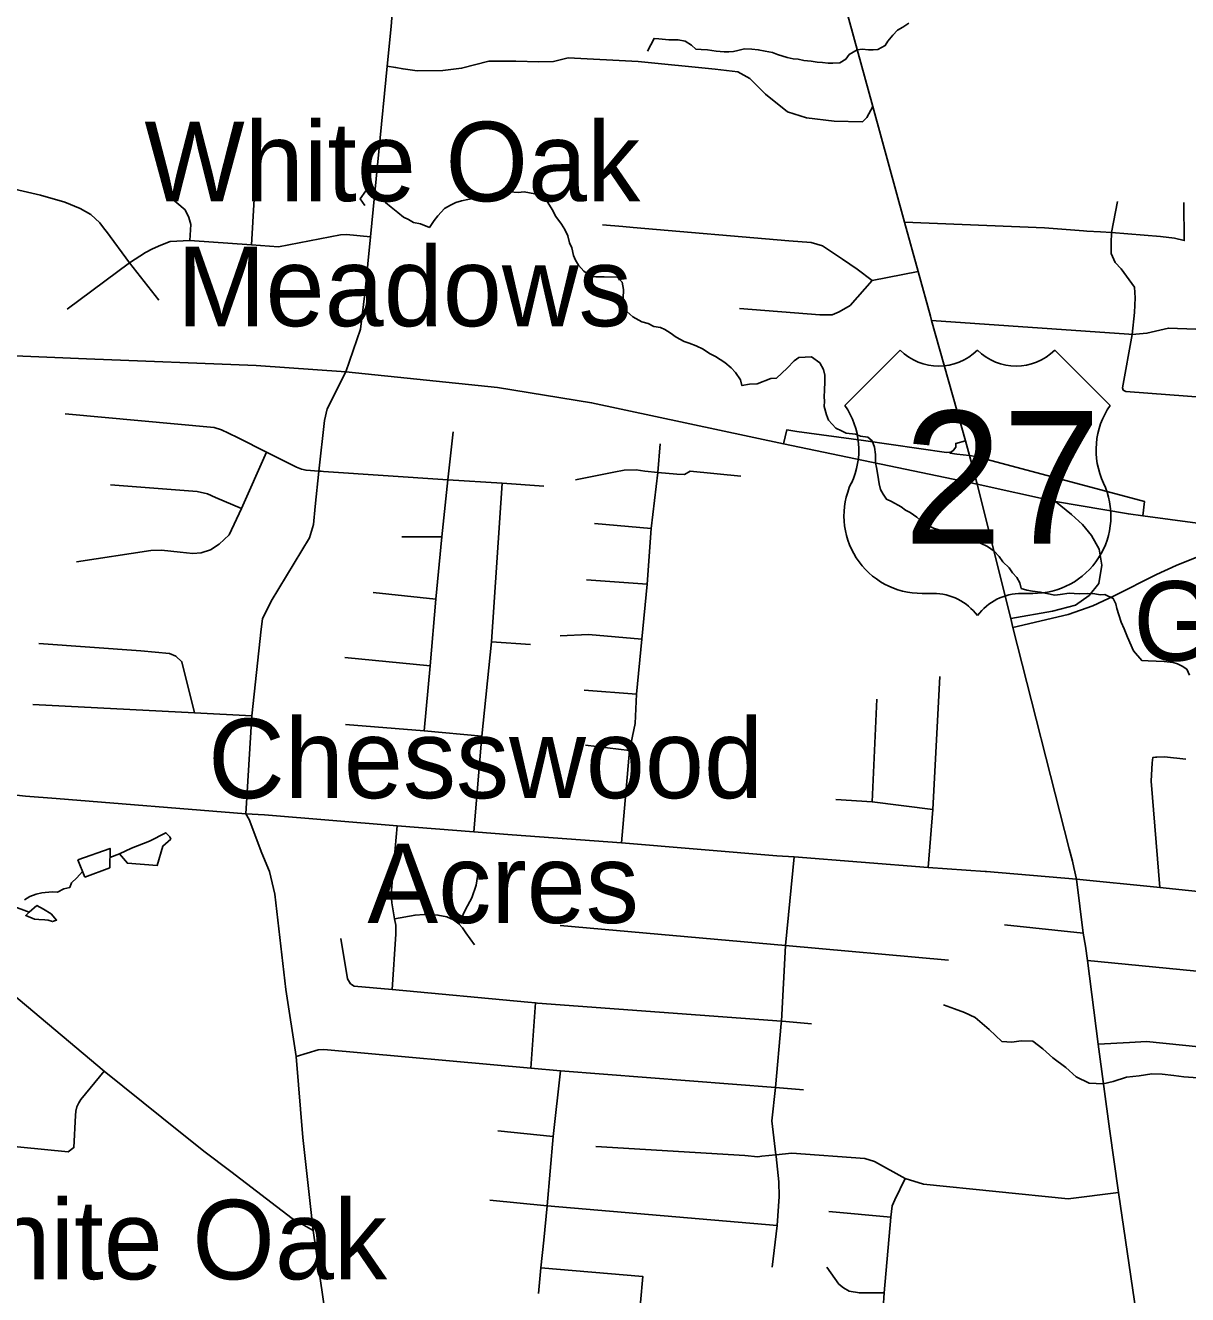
# Model space of a CAD drawing. Extents: x 0 to 69.5, y -4.5 to 22.
# Drawn here: x 3.408 to 4.564, y 15.023 to 16.285 of the extents above; entities that cross this region are included whole.
import ezdxf

# ---------------------------------------------------------------- set-up
doc = ezdxf.new("R2010")
doc.units = 0
for name, color, linetype in [('GM_X_County_Road', 7, 'Continuous'), ('GM_X_Interchange_Ramps', 7, 'Continuous'), ('GM_X_Minor_Lake', 7, 'Continuous'), ('GM_X_Minor_River', 7, 'Continuous'), ('GM_X_State_Route', 7, 'Continuous'), ('GM_X_Township_Subdivision', 7, 'Continuous'), ('GM_X_Unincorporated_Text', 7, 'Continuous'), ('GM_X_US_Location', 7, 'Continuous'), ('GM_X_US_Route', 7, 'Continuous'), ('GM_X_US_Shield', 7, 'Continuous')]:
    doc.layers.add(name, color=color, linetype=linetype)

msp = doc.modelspace()

# ---------------------------------------------------------------- linework, layer by layer
at = {"layer": 'GM_X_County_Road'}
for points in [[(3.6274, 15.5008), (3.6334, 15.5983), (3.6428, 15.6844), (3.6442, 15.6947), (3.6526, 15.7123), (3.6907, 15.7752), (3.6948, 15.7884), (3.6964, 15.8066), (3.7002, 15.8416), (3.7057, 15.8918), (3.7083, 15.9035), (3.7269, 15.9403), (3.7414, 15.9828), (3.7462, 16.0207), (3.7514, 16.0744), (3.7681, 16.2443), (3.7721, 16.2837), (3.7888, 16.4987)], [(3.7681, 16.2443), (3.7764, 16.243), (3.7839, 16.2415), (3.798, 16.2394), (3.8233, 16.2398), (3.8421, 16.2421), (3.8692, 16.2492), (3.8959, 16.2492), (3.9188, 16.2485), (3.9335, 16.2489), (3.9482, 16.2526), (4.0178, 16.2489), (4.0942, 16.2413), (4.1168, 16.2387), (4.1288, 16.2319), (4.1443, 16.2165), (4.1661, 16.1988), (4.1849, 16.1928), (4.2124, 16.1894), (4.2406, 16.1887), (4.2449, 16.193), (4.2509, 16.204)], [(2.0624, 16.1544), (2.0789, 16.1495), (2.3218, 16.0727), (2.3948, 16.0576), (2.5679, 16.0322), (2.6419, 16.0249), (2.8264, 16.0064), (2.913, 15.9963), (3.15, 15.9729), (3.2871, 15.9607), (3.469, 15.9531), (3.6377, 15.9467), (3.7269, 15.9403), (3.8777, 15.9247), (3.9714, 15.9095), (4.1621, 15.8689), (4.3548, 15.8285)], [(4.3548, 15.8285), (4.4326, 15.8115)], [(4.4326, 15.8115), (4.4486, 15.7985), (4.4596, 15.7885), (4.4686, 15.7775), (4.4761, 15.764), (4.4786, 15.748), (4.4756, 15.73), (4.4661, 15.718), (4.4526, 15.7085), (4.4296, 15.7025), (4.3881, 15.6951)], [(3.1437, 15.5578), (3.2132, 15.5475), (3.3147, 15.5315), (3.3657, 15.5231), (3.4084, 15.5185), (3.4388, 15.5162), (3.6274, 15.5008)], [(3.6945, 15.0867), (3.6842, 15.1793), (3.6775, 15.2598), (3.6674, 15.3264), (3.6565, 15.421), (3.6512, 15.4435), (3.6436, 15.4618), (3.631, 15.4952), (3.6274, 15.5008)], [(3.6274, 15.5008), (3.6461, 15.4998), (3.7781, 15.4889), (3.8541, 15.483), (3.8925, 15.4802), (4.001, 15.472), (4.1557, 15.4593), (4.1727, 15.4582), (4.306, 15.4477), (4.3627, 15.4437), (4.3641, 15.4436)], [(4.3641, 15.4436), (4.4536, 15.436)], [(4.4536, 15.436), (4.5333, 15.4281)], [(4.5333, 15.4281), (4.5365, 15.4278), (4.6218, 15.4186), (4.7103, 15.4103), (4.7637, 15.4056), (4.8525, 15.397), (4.9822, 15.3853), (5.1507, 15.3687)], [(3.3884, 15.3276), (3.4866, 15.245), (3.5439, 15.199), (3.5857, 15.1656), (3.6126, 15.1455), (3.6735, 15.0988), (3.6945, 15.0867)], [(3.6945, 15.0867), (3.7086, 14.9889), (3.7089, 14.9865), (3.7134, 14.9601), (3.7288, 14.8681), (3.7325, 14.8589)]]:
    msp.add_lwpolyline(points, dxfattribs=at)
at = {"layer": 'GM_X_Interchange_Ramps'}
for points in [[(4.343, 15.8718), (4.3335, 15.8691), (4.3334, 15.8655), (4.3313, 15.8624), (4.3291, 15.8608), (4.3276, 15.8605), (4.3243, 15.8601), (4.2417, 15.8721), (4.1754, 15.881), (4.1654, 15.8826), (4.1621, 15.8689)], [(4.347, 15.8571), (4.3347, 15.8584), (4.3278, 15.8595), (4.3276, 15.8605)], [(4.5196, 15.797), (4.5211, 15.8115), (4.3546, 15.8557), (4.347, 15.8571)]]:
    msp.add_lwpolyline(points, dxfattribs=at)
at = {"layer": 'GM_X_Minor_Lake'}
for points in [[(3.502, 15.461), (3.5098, 15.4518), (3.5394, 15.4496), (3.5451, 15.4689), (3.5529, 15.4759), (3.5518, 15.4779), (3.5481, 15.4821), (3.5319, 15.4737), (3.5139, 15.4669)], [(3.4673, 15.438), (3.4922, 15.4473), (3.4926, 15.4666), (3.4605, 15.4552)], [(3.5139, 15.4669), (3.502, 15.461)], [(3.4605, 15.4552), (3.4673, 15.438)], [(3.4122, 15.4033), (3.4087, 15.3998), (3.4174, 15.3961), (3.4216, 15.396), (3.4276, 15.3955), (3.431, 15.3951), (3.4352, 15.3938), (3.4394, 15.3953), (3.4338, 15.4015), (3.4263, 15.4062), (3.4197, 15.4099)], [(3.4197, 15.4099), (3.4122, 15.4033)]]:
    msp.add_lwpolyline(points, dxfattribs=at)
at = {"layer": 'GM_X_Minor_River'}
for points in [[(4.2868, 16.2868), (4.281, 16.2831), (4.2756, 16.2799), (4.2709, 16.275), (4.2658, 16.2691), (4.2634, 16.2646), (4.2561, 16.2606), (4.2515, 16.2604), (4.2466, 16.2605), (4.2405, 16.261), (4.2355, 16.2604), (4.2274, 16.2557), (4.2243, 16.2512), (4.2181, 16.2476), (4.2112, 16.247), (4.2067, 16.2471), (4.201, 16.2477), (4.1957, 16.2482), (4.1896, 16.2491), (4.1824, 16.2497), (4.1767, 16.251), (4.1718, 16.2515), (4.1657, 16.2529), (4.1563, 16.2558), (4.1514, 16.2578)], [(4.1514, 16.2578), (4.1439, 16.2592), (4.137, 16.2605), (4.1306, 16.2611), (4.1234, 16.2613), (4.1169, 16.2599), (4.1123, 16.2589), (4.1077, 16.2583), (4.1031, 16.2584), (4.0952, 16.259), (4.0865, 16.2604), (4.0804, 16.2609), (4.0751, 16.2611), (4.0706, 16.265), (4.0643, 16.269), (4.0574, 16.2703), (4.0483, 16.2702), (4.0381, 16.2713), (4.0335, 16.2718), (4.0271, 16.259)], [(4.1657, 15.944), (4.1552, 15.934), (4.1495, 15.9338), (4.136, 15.9285), (4.1284, 15.9279), (4.1208, 15.9266), (4.1194, 15.9324), (4.1143, 15.9397), (4.1102, 15.9444), (4.1039, 15.9495), (4.0945, 15.9555), (4.0885, 15.9587), (4.0822, 15.9627), (4.0754, 15.9663), (4.0683, 15.9688), (4.0634, 15.9705), (4.0555, 15.9749), (4.0495, 15.9792), (4.0443, 15.9824), (4.0398, 15.9845), (4.0334, 15.9854), (4.0277, 15.9882), (4.0213, 15.9899), (4.0123, 15.9951), (4.0064, 16.0003), (4.0031, 16.0064), (4.0029, 16.0133), (4.0032, 16.0221), (4.0019, 16.0293), (3.9967, 16.0344), (3.9837, 16.0348), (3.9758, 16.0346), (3.9705, 16.0355), (3.9637, 16.0403), (3.9582, 16.0465), (3.9553, 16.0512), (3.9535, 16.0558), (3.9518, 16.0635), (3.9493, 16.0685), (3.9476, 16.0754), (3.9447, 16.0819), (3.9414, 16.087), (3.9359, 16.0948), (3.9323, 16.1017), (3.9279, 16.1087), (3.9224, 16.1146), (3.9149, 16.1174), (3.9043, 16.1193), (3.8982, 16.1187), (3.8902, 16.1193), (3.8784, 16.1188), (3.8635, 16.1147), (3.8547, 16.113), (3.842, 16.1103), (3.8363, 16.1086), (3.8309, 16.1061), (3.8251, 16.1028), (3.8184, 16.0954), (3.8149, 16.0909), (3.8101, 16.0838), (3.8011, 16.0875), (3.7943, 16.0888), (3.7894, 16.0916), (3.7842, 16.094), (3.7786, 16.0988), (3.7719, 16.1039), (3.7663, 16.1086), (3.7586, 16.1169), (3.7522, 16.1201), (3.7469, 16.1202), (3.7413, 16.1124), (3.7457, 16.1058)], [(4.5659, 15.6389), (4.5634, 15.6446), (4.5585, 15.6478), (4.554, 15.6499), (4.5495, 15.6515), (4.5408, 15.6525), (4.5248, 15.653), (4.5184, 15.6535), (4.5102, 15.6629), (4.5041, 15.6764), (4.5009, 15.6848), (4.4981, 15.6914), (4.4956, 15.6987), (4.4935, 15.7052), (4.4925, 15.7098), (4.49, 15.7149), (4.4817, 15.7189), (4.4771, 15.7186), (4.4718, 15.7196), (4.4642, 15.7198), (4.4566, 15.7196), (4.4513, 15.7201), (4.4464, 15.7203), (4.4372, 15.719), (4.4319, 15.7184), (4.4239, 15.7201), (4.4175, 15.7214), (4.4099, 15.7224), (4.4043, 15.7233), (4.3986, 15.725), (4.3972, 15.7304), (4.3943, 15.7358), (4.3899, 15.7405), (4.3866, 15.7455), (4.3803, 15.7514), (4.3766, 15.7569), (4.3715, 15.762), (4.3651, 15.7667), (4.358, 15.7699), (4.3392, 15.7773), (4.3301, 15.7795), (4.3165, 15.7833), (4.3112, 15.785), (4.306, 15.7874), (4.3007, 15.7906), (4.2948, 15.7957), (4.2881, 15.8005), (4.2836, 15.8029), (4.2791, 15.806), (4.2697, 15.8113), (4.2645, 15.8137), (4.2612, 15.8187), (4.2587, 15.8234), (4.2573, 15.8291), (4.256, 15.8375), (4.2547, 15.8452), (4.2537, 15.8498), (4.2535, 15.8582), (4.2526, 15.8654), (4.2505, 15.8716), (4.246, 15.8755), (4.2388, 15.8765), (4.2339, 15.8785), (4.2244, 15.8795), (4.2199, 15.8816), (4.2143, 15.8844), (4.2069, 15.8922), (4.2048, 15.8976), (4.2027, 15.9057), (4.2029, 15.911), (4.2026, 15.9156), (4.2028, 15.922), (4.2034, 15.9304), (4.2032, 15.9369), (4.2018, 15.9426), (4.1982, 15.9492), (4.19, 15.9551), (4.1774, 15.9547), (4.1728, 15.9514), (4.1657, 15.944)], [(3.4924, 15.4574), (3.502, 15.461)], [(3.4075, 15.4153), (3.4126, 15.4186), (3.4191, 15.4211), (3.4248, 15.4224), (3.4348, 15.4233), (3.4401, 15.4232), (3.4466, 15.4264), (3.4524, 15.4278), (3.4543, 15.4322), (3.4594, 15.4372), (3.4651, 15.4435)], [(3.3865, 15.4148), (3.3953, 15.4094), (3.4122, 15.4033)], [(4.5741, 15.2384), (4.5604, 15.2395), (4.5502, 15.2409), (4.5388, 15.242), (4.5286, 15.2426), (4.516, 15.2406), (4.5034, 15.239), (4.49, 15.2348), (4.4801, 15.2324), (4.466, 15.2331), (4.4532, 15.2395), (4.4428, 15.2489), (4.4301, 15.2583), (4.4201, 15.2673), (4.41, 15.2748), (4.3986, 15.2754), (4.3891, 15.2741), (4.3792, 15.2747), (4.3666, 15.2865), (4.3528, 15.2986), (4.3423, 15.3034), (4.3321, 15.3071), (4.3212, 15.3111)]]:
    msp.add_lwpolyline(points, dxfattribs=at)
at = {"layer": 'GM_X_State_Route'}
for points in [[(4.4326, 15.8115), (4.5051, 15.799), (4.5196, 15.797), (4.6332, 15.782)], [(4.3903, 15.6863), (4.4453, 15.699), (4.4698, 15.7077), (4.4911, 15.7177), (4.5331, 15.7387), (4.5528, 15.7478), (4.5732, 15.7562), (4.5922, 15.7616), (4.6126, 15.7705), (4.6332, 15.782)]]:
    msp.add_lwpolyline(points, dxfattribs=at)
at = {"layer": 'GM_X_Township_Subdivision'}
for points in [[(3.4871, 16.0822), (3.4822, 16.0885), (3.4734, 16.0966), (3.4629, 16.1028), (3.4476, 16.1091), (3.4233, 16.1159), (3.4019, 16.1209), (3.362, 16.1302), (3.3606, 16.1298)], [(3.5718, 16.0708), (3.5727, 16.0867), (3.5708, 16.0938), (3.5671, 16.1013), (3.5487, 16.1168)], [(3.6331, 16.0664), (3.6359, 16.1119)], [(4.4605, 16.0806), (4.4639, 16.0803), (4.4773, 16.0796), (4.4885, 16.0787), (4.537, 16.0747), (4.5509, 16.0731), (4.5607, 16.0708), (4.5604, 16.1085)], [(4.4944, 16.1096), (4.4885, 16.0787), (4.4881, 16.0683), (4.488, 16.0579), (4.492, 16.0491), (4.498, 16.0426), (4.5111, 16.0246), (4.5119, 16.014), (4.5111, 15.9993), (4.5088, 15.9773), (4.4992, 15.9245), (4.4999, 15.9222), (4.5025, 15.9206), (4.669, 15.9083), (4.7263, 15.9033)], [(4.2826, 16.089), (4.4218, 16.0834), (4.4605, 16.0806)], [(3.4498, 16.0027), (3.5117, 16.0487), (3.5276, 16.059), (3.5347, 16.0627), (3.543, 16.0662), (3.5522, 16.0699), (3.5718, 16.0708), (3.6331, 16.0664), (3.6601, 16.0646), (3.7217, 16.0764), (3.7277, 16.0769), (3.7514, 16.0744)], [(3.541, 16.0114), (3.5117, 16.0487), (3.489, 16.0798), (3.4871, 16.0822)], [(4.0025, 16.0848), (3.9822, 16.0866)], [(4.2961, 16.0399), (4.2505, 16.0312), (4.2355, 16.0424), (4.2208, 16.0524), (4.2011, 16.0656), (4.1896, 16.0689), (4.1676, 16.0707), (4.0126, 16.0839), (4.0025, 16.0848)], [(4.1185, 16.0034), (4.1982, 15.997), (4.2105, 15.9971), (4.2175, 16.0001), (4.2284, 16.0064), (4.2505, 16.0312)], [(4.3094, 15.9915), (4.5055, 15.9776)], [(4.5055, 15.9776), (4.5088, 15.9773), (4.5235, 15.9786), (4.545, 15.9838), (4.5904, 15.982), (4.6449, 15.9751), (4.6518, 15.9745)], [(3.448, 15.8985), (3.5959, 15.885), (3.6034, 15.8826), (3.6102, 15.8793), (3.6199, 15.8746), (3.6481, 15.8604), (3.678, 15.8454), (3.6829, 15.8434), (3.6874, 15.8425), (3.7002, 15.8416), (3.7025, 15.8415), (3.7048, 15.8413)], [(3.8047, 15.5833), (3.8107, 15.6481), (3.8165, 15.7144), (3.8224, 15.7763), (3.8285, 15.8331), (3.8336, 15.8806)], [(3.6481, 15.8604), (3.6231, 15.8043), (3.6108, 15.7783), (3.6011, 15.7689), (3.5923, 15.7634), (3.5831, 15.7604), (3.5747, 15.7598), (3.5621, 15.761), (3.5436, 15.7629), (3.5332, 15.7628), (3.459, 15.7513)], [(4.001, 15.472), (4.0089, 15.5639), (4.0147, 15.5907), (4.0159, 15.62), (4.0213, 15.6745), (4.0266, 15.7292), (4.0305, 15.7846), (4.0373, 15.8404), (4.0397, 15.8686)], [(3.7048, 15.8413), (3.8285, 15.8331), (3.8824, 15.8295), (3.9238, 15.8267)], [(3.9555, 15.8328), (3.9935, 15.8407), (4.0037, 15.8424), (4.0156, 15.8428), (4.0244, 15.8417), (4.0373, 15.8404), (4.0562, 15.8385), (4.0639, 15.8383), (4.0695, 15.8416), (4.1198, 15.8367)], [(3.6231, 15.8043), (3.5973, 15.8153), (3.5895, 15.8191), (3.5792, 15.8213), (3.493, 15.8281)], [(3.8541, 15.483), (3.8621, 15.5782), (3.8718, 15.672), (3.8824, 15.8295)], [(4.0305, 15.7846), (3.9744, 15.7894)], [(3.8224, 15.7763), (3.7825, 15.7763)], [(3.9662, 15.7337), (4.0266, 15.7292)], [(3.8165, 15.7144), (3.7542, 15.7208)], [(3.8718, 15.672), (3.9107, 15.6694)], [(3.9401, 15.6778), (3.9683, 15.6793), (4.0213, 15.6745)], [(3.5764, 15.6013), (3.564, 15.6521), (3.5579, 15.6576), (3.5517, 15.6602), (3.5231, 15.6629), (3.4216, 15.6702)], [(3.8107, 15.6481), (3.726, 15.6562)], [(4.306, 15.4477), (4.3107, 15.5051), (4.3175, 15.6376)], [(4.0159, 15.62), (3.9639, 15.6238)], [(3.6334, 15.5983), (3.5764, 15.6013), (3.4156, 15.6096)], [(4.2504, 15.5127), (4.255, 15.6149)], [(3.8621, 15.5782), (3.8047, 15.5833), (3.7268, 15.5897)], [(4.0089, 15.5639), (3.9654, 15.5691)], [(4.5321, 15.5571), (4.5335, 15.5572), (4.5412, 15.5577), (4.5624, 15.5552)], [(4.5365, 15.4278), (4.5278, 15.5333), (4.5288, 15.5516), (4.5293, 15.5568), (4.5321, 15.5571)], [(4.3107, 15.5051), (4.2504, 15.5127), (4.2141, 15.5153)], [(3.7732, 15.3262), (3.7768, 15.3814), (3.7766, 15.3901), (3.7754, 15.3964), (3.7746, 15.4004), (3.7726, 15.4123), (3.772, 15.421), (3.7729, 15.4327), (3.7781, 15.4889)], [(4.1727, 15.4582), (4.1643, 15.37), (4.1602, 15.2947), (4.16, 15.2925)], [(3.8393, 15.3915), (3.8461, 15.4059), (3.8524, 15.4175), (3.8565, 15.4299), (3.8592, 15.4473)], [(3.7754, 15.3964), (3.7959, 15.4003), (3.8049, 15.401), (3.8059, 15.401)], [(3.8059, 15.401), (3.8094, 15.401), (3.8186, 15.4003), (3.8273, 15.3984), (3.8341, 15.3956), (3.8393, 15.3915), (3.8429, 15.3875), (3.8464, 15.3826), (3.855, 15.3707)], [(3.9401, 15.3899), (4.1643, 15.37), (4.3263, 15.3556)], [(4.4601, 15.3824), (4.382, 15.3906)], [(3.908, 15.3136), (3.7732, 15.3262), (3.7352, 15.3296), (3.7315, 15.332), (3.7286, 15.337), (3.722, 15.3771)], [(4.6365, 15.3382), (4.6244, 15.3396), (4.4644, 15.355)], [(3.9177, 15.3128), (3.9155, 15.3129), (3.908, 15.3136)], [(3.911, 15.248), (3.9155, 15.3129)], [(4.1609, 15.2947), (4.1602, 15.2947), (3.9177, 15.3128)], [(4.16, 15.2925), (4.1543, 15.2289), (4.1505, 15.1956), (4.1547, 15.162), (4.1549, 15.1603)], [(4.1901, 15.2921), (4.1609, 15.2947)], [(4.4752, 15.2718), (4.5061, 15.2736), (4.523, 15.2745), (4.5946, 15.2672)], [(4.182, 15.2266), (4.1543, 15.2289), (3.9403, 15.2453), (3.911, 15.248), (3.7052, 15.2666), (3.6995, 15.2663), (3.6775, 15.2598)], [(3.3433, 15.1746), (3.3838, 15.1717), (3.4039, 15.1695), (3.4508, 15.1648), (3.4566, 15.1692), (3.4581, 15.201), (3.4585, 15.2052), (3.4596, 15.2095), (3.4615, 15.2137), (3.4636, 15.2171), (3.4866, 15.245)], [(3.9237, 15.0772), (3.9271, 15.1113), (3.9331, 15.18), (3.9403, 15.2453)], [(3.878, 15.1859), (3.9331, 15.18)], [(4.1407, 15.1605), (4.1367, 15.16), (4.1236, 15.1612), (3.9756, 15.1702)], [(4.4954, 15.1244), (4.4454, 15.1183), (4.3015, 15.1329), (4.2831, 15.1383), (4.2528, 15.1554), (4.2429, 15.1584), (4.1706, 15.1636), (4.1547, 15.162), (4.1407, 15.1605)], [(4.1549, 15.1603), (4.1575, 15.135), (4.158, 15.1205), (4.1558, 15.0917), (4.1508, 15.0501)], [(4.1976, 14.8897), (4.2019, 14.9169), (4.2042, 14.9255), (4.2086, 14.9327), (4.254, 14.9884), (4.2586, 14.9962), (4.2613, 15.0095), (4.2622, 15.0246), (4.2689, 15.1001), (4.2701, 15.1112), (4.2729, 15.1172), (4.2831, 15.1383)], [(4.1558, 15.0917), (3.9271, 15.1113), (3.8703, 15.117)], [(4.2073, 15.1056), (4.2689, 15.1001)], [(3.9185, 15.0241), (3.921, 15.0495), (3.9237, 15.0772)], [(4.0106, 14.9118), (4.0222, 15.0411), (3.921, 15.0495)], [(4.2622, 15.0246), (4.2377, 15.0246), (4.2276, 15.0263), (4.222, 15.0296), (4.2171, 15.0334), (4.2053, 15.0503)]]:
    msp.add_lwpolyline(points, dxfattribs=at)
at = {"layer": 'GM_X_US_Route'}
for points in [[(4.347, 15.8571), (4.343, 15.8718), (4.3094, 15.9915), (4.3082, 15.9958), (4.2961, 16.0399), (4.2826, 16.089), (4.2509, 16.204), (4.2124, 16.3441), (4.1884, 16.4342), (4.1794, 16.4679), (4.1431, 16.6089), (4.0889, 16.8066), (4.0359, 17.0028), (4.0043, 17.1198), (3.9604, 17.2824), (3.9324, 17.3858)], [(4.3548, 15.8285), (4.347, 15.8571)], [(4.3903, 15.6863), (4.3881, 15.6951), (4.3548, 15.8285)], [(4.4494, 15.4539), (4.4464, 15.4662), (4.3903, 15.6863)], [(4.5242, 14.9225), (4.5208, 14.9494), (4.5159, 14.9833), (4.5144, 14.9937), (4.4954, 15.1244), (4.4862, 15.1877), (4.4752, 15.2718), (4.4644, 15.355), (4.4625, 15.3694), (4.4601, 15.3824), (4.4536, 15.436), (4.4509, 15.4477), (4.4494, 15.4539)]]:
    msp.add_lwpolyline(points, dxfattribs=at)
at = {"layer": 'GM_X_US_Shield'}
for p, q in [((4.2781, 15.9618), (4.2232, 15.9068)), ((4.4869, 15.9068), (4.4319, 15.9618)), ((4.3001, 15.7201), (4.3111, 15.7201)), ((4.399, 15.7201), (4.41, 15.7201))]:
    msp.add_line(p, q, dxfattribs=at)
for centre, radius, start, end in [((4.3166, 16.001), 0.0549, 225.573, 314.427), ((4.3935, 16.001), 0.0549, 225.573, 314.427), ((4.1602, 15.8627), 0.0769, 334.5471, 35.0009), ((4.5499, 15.8627), 0.0769, 144.9991, 205.4529), ((4.2992, 15.797), 0.0769, 154.8319, 270.6383), ((4.4108, 15.797), 0.0769, 269.3617, 25.1681), ((4.3111, 15.6651), 0.0549, 36.8699, 90), ((4.399, 15.6651), 0.0549, 90, 143.1301)]:
    msp.add_arc(centre, radius, start, end, dxfattribs=at)

# ---------------------------------------------------------------- texts
at = {"layer": 'GM_X_Unincorporated_Text'}
for s, p in [('White Oak', (3.5267, 16.1099)), ('Meadows', (3.5592, 15.9857)), ('Groesbeck', (4.51, 15.6532)), ('Chesswood', (3.59, 15.5165)), ('Acres', (3.7484, 15.3924)), ('White Oak', (3.275, 15.0382))]:
    msp.add_text(s, height=0.07898, rotation=0, dxfattribs=at).set_placement(p)
at = {"layer": 'GM_X_US_Location'}
for s in ['0', '/']:
    msp.add_text(s, height=0.000189, dxfattribs=at).set_placement((4.355, 15.8344))
msp.add_text('27', height=0.000189, rotation=0, dxfattribs=at).set_placement((4.3159, 15.7952))
at = {"layer": 'GM_X_US_Shield'}
msp.add_text('27', height=0.13184, dxfattribs=at).set_placement((4.2817, 15.7695))

doc.saveas('drawing.dxf')
